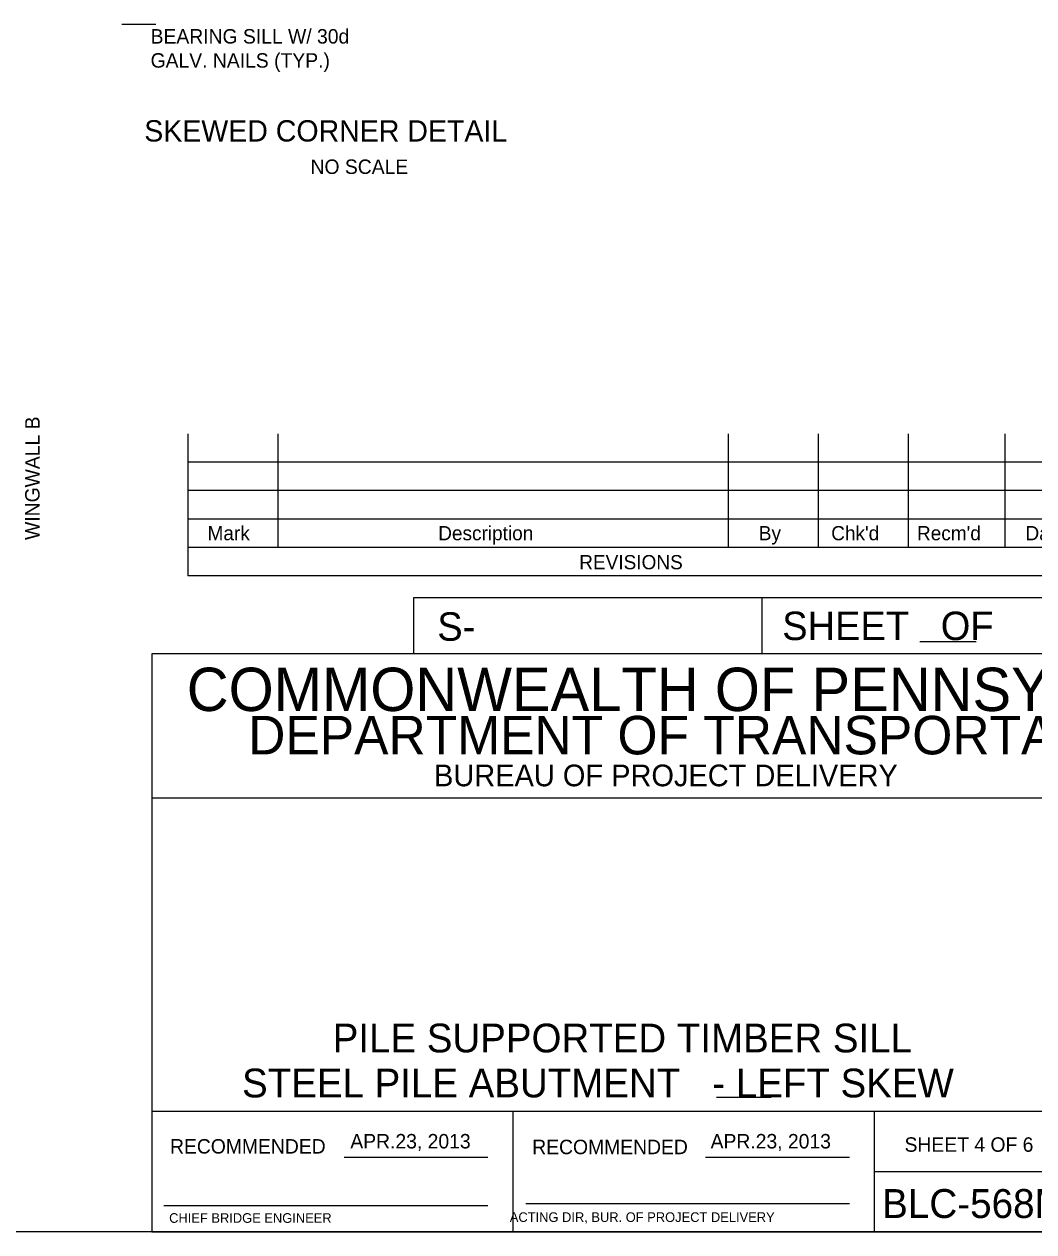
# Model space of a CAD drawing. Extents: x 638304 to 640306, y 296653 to 298435.
# Drawn here: x 639875.9 to 640085.6, y 297856.5 to 298107.2 of the extents above; entities that cross this region are included whole.
import ezdxf

# ---------------------------------------------------------------- set-up
doc = ezdxf.new("R2010")
doc.units = 0
for name, color, linetype in [('2', 7, 'Continuous'), ('4', 7, 'Continuous'), ('Level 4', 7, 'Continuous'), ('Level 5', 7, 'Continuous')]:
    doc.layers.add(name, color=color, linetype=linetype)

msp = doc.modelspace()

# ---------------------------------------------------------------- linework, layer by layer
at = {"layer": '2'}
for p, q in [((639909.92, 298022.15), (639909.92, 297992.62)), ((639928.62, 298022.15), (639928.62, 297998.53)), ((640022.13, 298022.15), (640022.13, 297998.53)), ((640040.83, 298022.15), (640040.83, 297998.53)), ((640059.53, 298022.15), (640059.53, 297998.53)), ((640079.59, 298022.15), (640079.59, 297998.53)), ((640096.94, 298016.24), (639909.92, 298016.24)), ((640096.94, 298010.34), (639909.92, 298010.34)), ((640096.94, 298004.43), (639909.92, 298004.43)), ((640096.94, 297998.53), (639909.92, 297998.53)), ((640096.94, 297992.62), (639909.92, 297992.62)), ((640102.46, 297988.11), (639956.78, 297988.11)), ((639956.78, 297988.11), (639956.78, 297976.46)), ((640029.09, 297988.11), (640029.09, 297976.46)), ((640061.95, 297979), (640073.6, 297979)), ((640102.46, 297976.46), (639902.46, 297976.46)), ((639902.46, 297976.46), (639902.46, 297856.46)), ((640102.46, 297946.46), (639902.46, 297946.46)), ((640102.46, 297881.46), (639902.46, 297881.46)), ((639977.46, 297856.46), (639977.46, 297881.46)), ((640052.46, 297881.46), (640052.46, 297856.46)), ((639942.42, 297871.96), (639972.19, 297871.96)), ((640017.42, 297871.96), (640047.33, 297871.96)), ((640052.46, 297868.96), (640102.46, 297868.96)), ((639904.96, 297861.96), (639972.19, 297861.96)), ((639980.08, 297862.33), (640047.33, 297862.33)), ((640102.46, 297856.46), (639316.46, 297856.46)), ((639902.46, 297856.46), (640102.46, 297856.46))]:
    msp.add_line(p, q, dxfattribs=at)
at = {"layer": '4'}
msp.add_line((640019.69, 297884.41), (640031.05, 297884.41), dxfattribs=at)
at = {"layer": 'Level 4'}
msp.add_line((639896.26, 298107.18), (639903.31, 298107.18), dxfattribs=at)

# ---------------------------------------------------------------- texts
at = {"layer": '2'}
for s, height, p in [('Mark', 2.952, (639914.02, 298000.03)), ('Description', 2.9523, (639961.92, 298000.03)), ('By', 2.952, (640028.49, 298000.03)), ("Chk'd", 2.952, (640043.52, 298000.03)), ("Recm'd", 2.953, (640061.33, 298000.03)), ('Date', 2.952, (640083.86, 298000.03)), ('REVISIONS', 2.952, (639991.2, 297994.01)), ('S-', 5.905, (639961.73, 297979.17)), ('COMMONWEALTH OF PENNSYLVANIA', 9, (639909.71, 297964.58)), ('DEPARTMENT OF TRANSPORTATION', 8.0002, (639922.46, 297955.58)), ('BUREAU OF PROJECT DELIVERY', 4.5, (639961.05, 297948.96)), ('STEEL PILE ABUTMENT   - LEFT SKEW', 5.9728, (639921.19, 297884.37)), ('APR.23, 2013', 3, (639943.67, 297873.77)), ('APR.23, 2013', 3, (640018.48, 297873.77)), ('SHEET 4 OF 6', 3, (640058.75, 297873.08)), ('BLC-568M', 6, (640054.08, 297859.33)), ('CHIEF BRIDGE ENGINEER', 2.0002, (639906.05, 297858.33)), ('  ACTING DIR, BUR. OF PROJECT DELIVERY', 2.0002, (639975.3, 297858.51))]:
    msp.add_text(s, height=height, dxfattribs=at).set_placement(p)
for s, height, p in [('SHEET   OF', 5.907, (640033.35, 297979.31)), ('RECOMMENDED', 3, (639906.23, 297872.71)), ('RECOMMENDED', 3, (639981.44, 297872.58))]:
    msp.add_text(s, height=height, rotation=360, dxfattribs=at).set_placement(p)
at = {"layer": '4'}
for s, height, p in [('SKEWED CORNER DETAIL', 4.4294, (639900.88, 298082.81)), ('NO SCALE', 3, (639935.41, 298076.08)), ('PILE SUPPORTED TIMBER SILL', 5.9728, (639940.01, 297893.71))]:
    msp.add_text(s, height=height, dxfattribs=at).set_placement(p)
at = {"layer": 'Level 4'}
msp.add_text('WINGWALL B', height=3, rotation=89.9382, dxfattribs=at).set_placement((639879.14, 298000.09))
at = {"layer": 'Level 5'}
for s, p in [('BEARING SILL W/ 30d', (639902.2, 298103.15)), ('GALV. NAILS (TYP.)', (639902.2, 298098.15))]:
    msp.add_text(s, height=3.0001, dxfattribs=at).set_placement(p)

doc.saveas('drawing.dxf')
